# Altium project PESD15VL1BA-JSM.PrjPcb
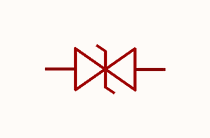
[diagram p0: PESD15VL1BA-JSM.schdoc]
1 sheet, 1 parts. Net scope: global (net labels, ports and power ports of the same name join across sheets).

## Sheet PESD15VL1BA-JSM.schdoc
size 127 x 101 mm

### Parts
D?  pesd15vl1ba-jsm  [SOD-323F_L1.7-W1.3-LS2.5-BI]  (value not drawn)

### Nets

Not connected (* = marked no-connect by the designer): D? 1 2

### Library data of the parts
D? = pesd15vl1ba-jsm: 极性:双向;反向截止电压(Vrwm):15V;钳位电压:32V;峰值脉冲电流(Ipp):10A@8/20us;峰值脉冲功率(Ppp):320W@8/20us;击穿电压(VBR):16.7V;; Manufacturer: JSMSEMI(杰盛微); AddInBom: yes; Polarity: 双向; Reverse Stand-Off Voltage (Vrwm): 15V; Clamping Voltage: 32V; Voltage - Breakdown: 16.7V; Reverse Leakage Current (Ir): 500nA; level of protection: IEC 61000-4-4；IEC 61000-4-5；IEC 61000-4-2; Type: ESD; Junction Capacitance: 20pF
